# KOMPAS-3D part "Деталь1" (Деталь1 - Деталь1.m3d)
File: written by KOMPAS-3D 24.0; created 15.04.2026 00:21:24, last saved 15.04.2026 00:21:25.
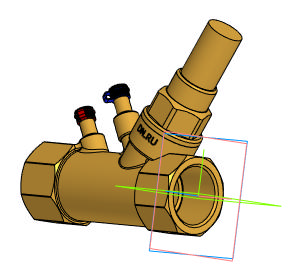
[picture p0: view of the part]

Document properties: Автор: tyuri; Полное имя файла: D:\Аутсорс\VB0000P-T Клапан балансировочный статический DN.ru\DN25\Деталь1 - Деталь1.m3d

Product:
- Body: Твердое тело1  | qty 1
    Масса: 0.566734
- Part/product: Деталь1
    Масса: 0.566734
    additional columns: Типовые

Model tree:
1. Твердое тело1  (labels: Твердое тело1)
2. Изменить положение граней:1  (labels: Грань.Твердое тело1)
     Расстояние = 1.5
3. Изменить положение граней:2  (labels: Грань.Твердое тело1)
     Расстояние = 1.5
